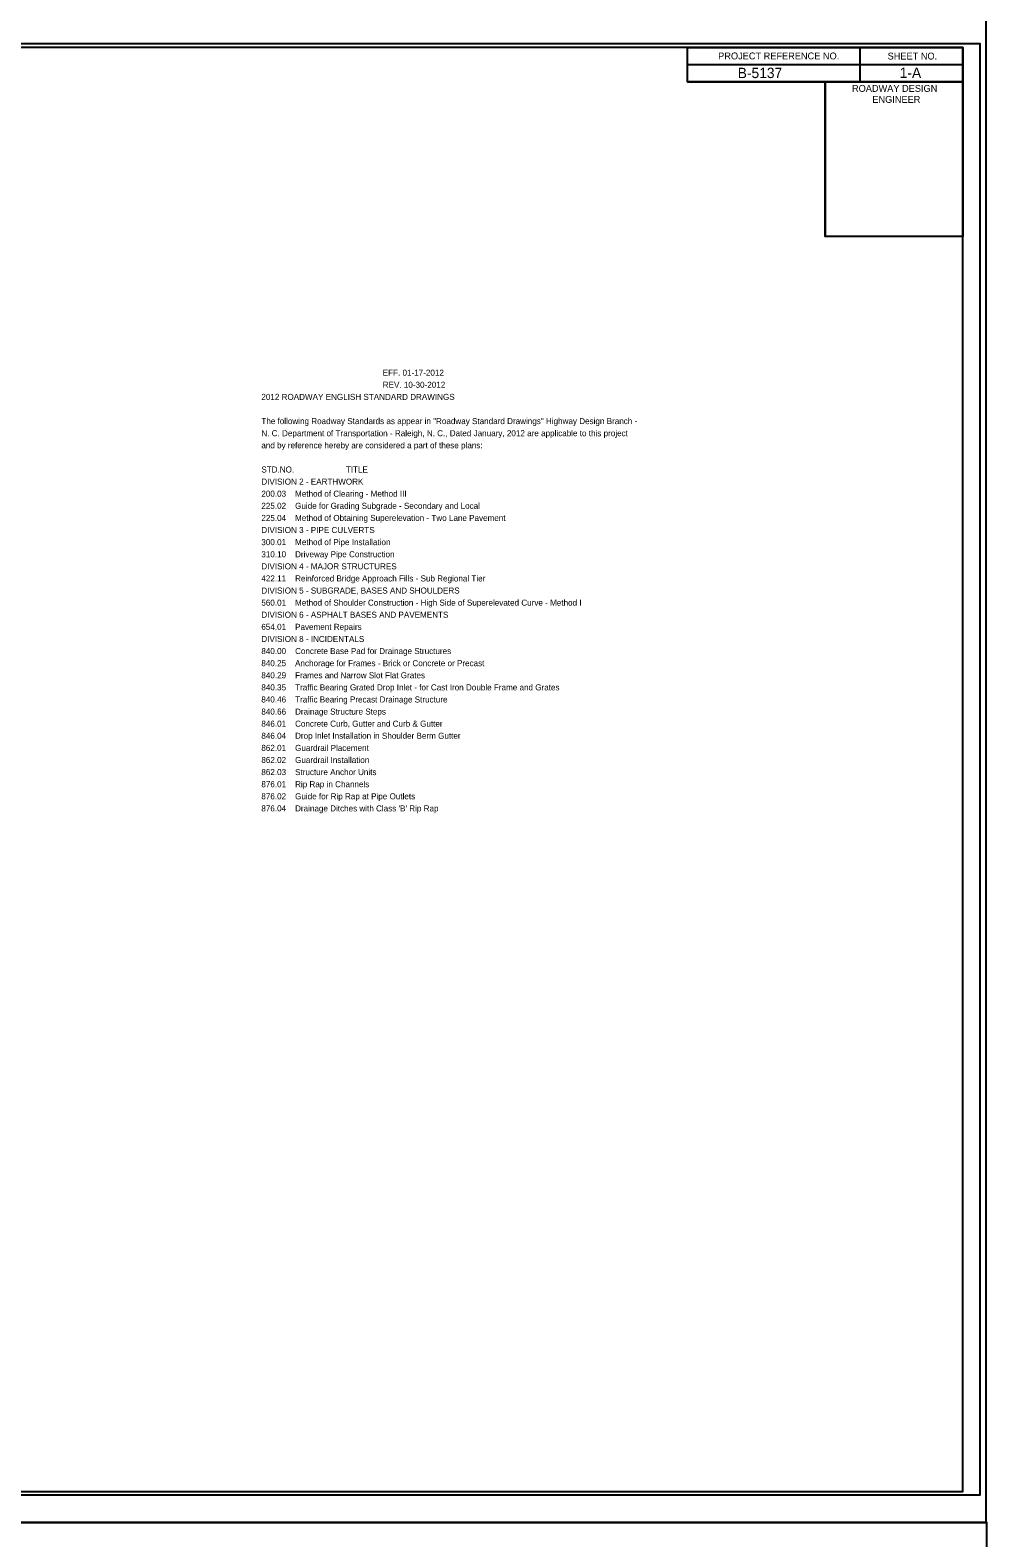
# Model space of a CAD drawing. Extents: x 1664524 to 1666208, y 587901 to 592296.
# Drawn here: x 1665512 to 1666208, y 590090 to 591186 of the extents above; entities that cross this region are included whole.
import ezdxf

# ---------------------------------------------------------------- set-up
doc = ezdxf.new("R2010")
doc.units = 0
for name, color, linetype in [('Old_Level_11', 7, 'Continuous'), ('Prop Horizontal Alignment', 7, 'Continuous'), ('Prop Horizontal Alignment Tick Large', 7, 'Continuous'), ('Prop Horizontal Alignment Tick Small', 7, 'Continuous'), ('Sheet Cutting Line CELL', 7, 'Continuous'), ('Sheet Plan CELL', 7, 'Continuous')]:
    doc.layers.add(name, color=color, linetype=linetype)

msp = doc.modelspace()

# ---------------------------------------------------------------- linework, layer by layer
at = {"layer": 'Prop Horizontal Alignment Tick Large'}
msp.add_lwpolyline([(1664536.8, 590121.3), (1666202.8, 590121.3), (1666202.8, 591176.3), (1664536.8, 591176.3)], close=True, dxfattribs=at)
at = {"layer": 'Prop Horizontal Alignment Tick Small'}
for points in [[(1664523.8, 590101.3), (1666207.3, 590101.3), (1666207.3, 591196.3), (1664523.8, 591196.3)], [(1664523.8, 589001.3), (1666207.8, 589001.3), (1666207.8, 590101.3), (1664523.8, 590101.3)]]:
    msp.add_lwpolyline(points, close=True, dxfattribs=at)
at = {"layer": 'Sheet Cutting Line CELL'}
for p, q in [((1666207.8, 590101.3), (1664523.8, 590101.3)), ((1664523.8, 590101.3), (1666207.3, 590101.3))]:
    msp.add_line(p, q, dxfattribs=at)
at = {"layer": 'Sheet Plan CELL'}
for p, q in [((1666115.3, 591173.8), (1666115.3, 591148.8)), ((1665990.2, 591161.3), (1666190.3, 591161.3)), ((1665990.2, 591148.8), (1666190.3, 591148.8)), ((1665990.2, 591148.8), (1666190.3, 591148.8)), ((1666090.3, 591148.8), (1666090.3, 591036.3))]:
    msp.add_line(p, q, dxfattribs=at)
for points in [[(1666190.3, 591173.8), (1664690.3, 591173.8), (1664690.3, 590123.8), (1666190.3, 590123.8)], [(1665990.2, 591173.8), (1666190.3, 591173.8), (1666190.3, 591148.8), (1665990.2, 591148.8)], [(1666090.3, 591148.8), (1666190.3, 591148.8), (1666190.3, 591036.3), (1666090.3, 591036.3)]]:
    msp.add_lwpolyline(points, close=True, dxfattribs=at)

# ---------------------------------------------------------------- texts
at = {"layer": 'Old_Level_11'}
for s, p in [('                                                      EFF. 01-17-2012', (1665680.2, 590935.1)), ('2012 ROADWAY ENGLISH STANDARD DRAWINGS', (1665680.2, 590917.5)), ('                                                      REV. 10-30-2012', (1665680.2, 590926.3)), ('The following Roadway Standards as appear in "Roadway Standard Drawings" Highway Design Branch -', (1665680.2, 590899.9)), ('N. C. Department of Transportation - Raleigh, N. C., Dated January, 2012 are applicable to this project', (1665680.2, 590891.1)), ('and by reference hereby are considered a part of these plans:', (1665680.2, 590882.3)), ('STD.NO.                       TITLE', (1665680.2, 590864.7)), ('DIVISION 2 - EARTHWORK', (1665680.2, 590855.9)), ('200.03    Method of Clearing - Method III', (1665680.2, 590847.1)), ('225.02    Guide for Grading Subgrade - Secondary and Local', (1665680.2, 590838.3)), ('225.04    Method of Obtaining Superelevation - Two Lane Pavement', (1665680.2, 590829.5)), ('DIVISION 3 - PIPE CULVERTS', (1665680.2, 590820.7)), ('300.01    Method of Pipe Installation ', (1665680.2, 590811.9)), ('310.10    Driveway Pipe Construction ', (1665680.2, 590803.1)), ('422.11    Reinforced Bridge Approach Fills - Sub Regional Tier', (1665680.2, 590785.5)), ('DIVISION 4 - MAJOR STRUCTURES', (1665680.2, 590794.3)), ('DIVISION 5 - SUBGRADE, BASES AND SHOULDERS', (1665680.2, 590776.7)), ('560.01    Method of Shoulder Construction - High Side of Superelevated Curve - Method I', (1665680.2, 590767.9)), ('DIVISION 6 - ASPHALT BASES AND PAVEMENTS', (1665680.2, 590759.1)), ('654.01    Pavement Repairs', (1665680.2, 590750.3)), ('DIVISION 8 - INCIDENTALS', (1665680.2, 590741.5)), ('840.00    Concrete Base Pad for Drainage Structures', (1665680.2, 590732.7)), ('840.25    Anchorage for Frames - Brick or Concrete or Precast', (1665680.2, 590723.9)), ('840.29    Frames and Narrow Slot Flat Grates', (1665680.2, 590715.1)), ('840.35    Traffic Bearing Grated Drop Inlet - for Cast Iron Double Frame and Grates', (1665680.2, 590706.3)), ('840.46    Traffic Bearing Precast Drainage Structure', (1665680.2, 590697.5)), ('840.66    Drainage Structure Steps', (1665680.2, 590688.7)), ('846.01    Concrete Curb, Gutter and Curb & Gutter', (1665680.2, 590679.9)), ('846.04    Drop Inlet Installation in Shoulder Berm Gutter', (1665680.2, 590671.1)), ('862.01    Guardrail Placement', (1665680.2, 590662.3)), ('862.02    Guardrail Installation', (1665680.2, 590653.5)), ('862.03    Structure Anchor Units', (1665680.2, 590644.7)), ('876.01    Rip Rap in Channels', (1665680.2, 590635.9)), ('876.02    Guide for Rip Rap at Pipe Outlets', (1665680.2, 590627.1)), ("876.04    Drainage Ditches with Class 'B' Rip Rap", (1665680.2, 590618.3))]:
    msp.add_text(s, height=4.4, rotation=360, dxfattribs=at).set_placement(p)
at = {"layer": 'Prop Horizontal Alignment'}
for s, p in [('B-5137   ', (1666026.6, 591151.5)), ('1-A', (1666144.4, 591151.6))]:
    msp.add_text(s, height=7.5, dxfattribs=at).set_placement(p)
at = {"layer": 'Sheet Plan CELL'}
for s, p in [('PROJECT REFERENCE NO.', (1666012.4, 591165.1)), ('SHEET NO.', (1666135.6, 591165)), ('ROADWAY DESIGN', (1666109.7, 591141.5)), ('ENGINEER', (1666124.5, 591133.5))]:
    msp.add_text(s, height=5, dxfattribs=at).set_placement(p)

doc.saveas('drawing.dxf')
